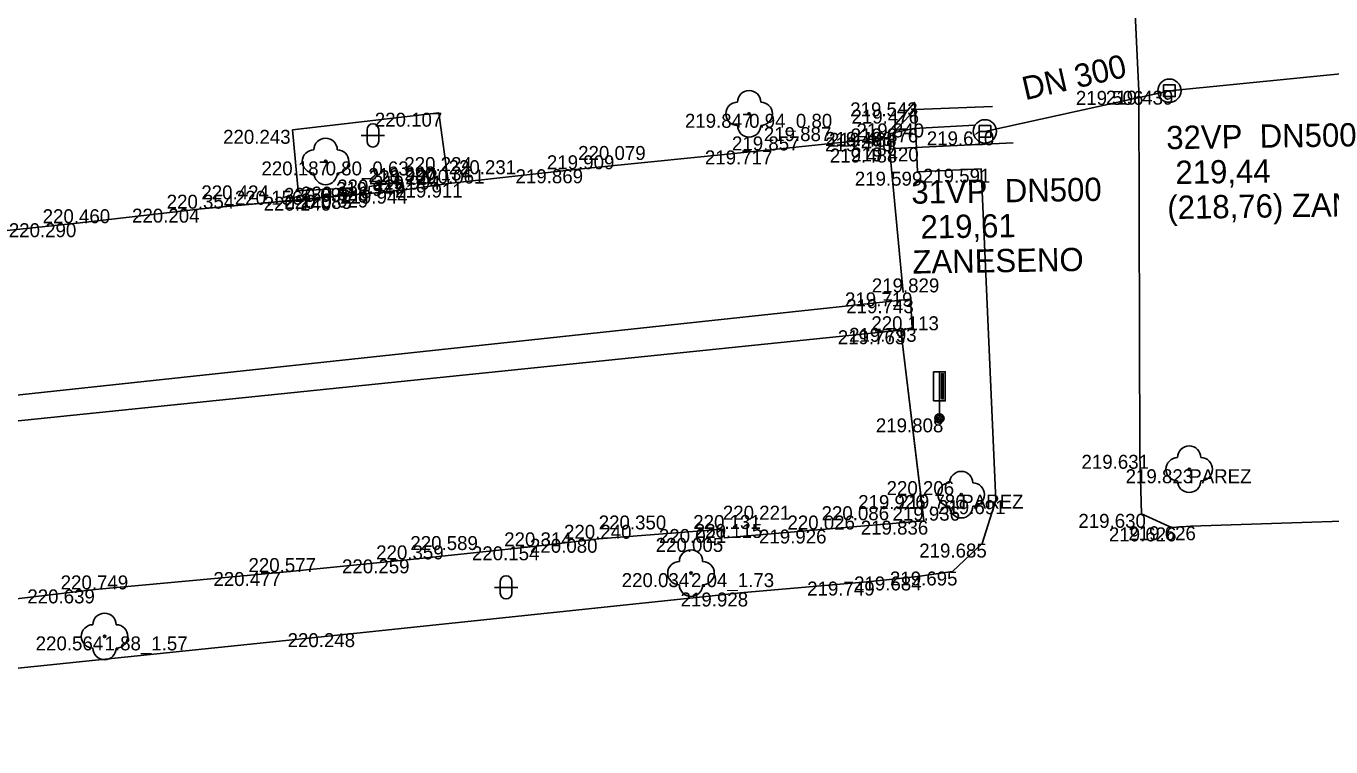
# Model space of a CAD drawing. Extents: x -599516 to -599132, y -1163668 to -1163119.
# Drawn here: x -599267.3 to -599239.27, y -1163495.5 to -1163480.02 of the extents above; entities that cross this region are included whole.
import ezdxf

# ---------------------------------------------------------------- set-up
doc = ezdxf.new("R2010")
doc.units = 0
for name, color, linetype in [('Bod-oznac1', 7, 'Continuous'), ('Bod-oznac2', 7, 'Continuous'), ('Bod-oznac3', 7, 'Continuous'), ('Bod-oznac4', 7, 'Continuous'), ('Bod-vyska1', 7, 'Continuous'), ('Bod-vyska2', 7, 'Continuous'), ('Bod-vyska3', 7, 'Continuous'), ('Bod-vyska4', 7, 'Continuous'), ('Z_cela-hrobu-dolni-linie', 7, 'Continuous'), ('Z_cela-hrobu-horni-linie', 7, 'Continuous'), ('Z_kanalizace-destova', 7, 'Continuous'), ('Z_kanalizace-znacky-vpust', 7, 'Continuous'), ('Z_komunikace', 7, 'Continuous'), ('Z_kultury-znacky', 7, 'Continuous'), ('Z_obvod-kmene-spodek-ve-vysce1_2m', 7, 'Continuous'), ('Z_parez-stromu', 7, 'Continuous'), ('Z_podzemni-obrys-sachty', 7, 'Continuous'), ('Z_stromy-kere', 7, 'Continuous'), ('Z_zdi-ohradni', 7, 'Continuous'), ('Z_zlaby-odvodneni', 7, 'Continuous'), ('Z_zlaby-odvodneni-osa', 7, 'Continuous'), ('Z_zlaby-odvodneni-zakryte-hrany', 7, 'Continuous'), ('Z_znacky-ostatni-orientacni-sloupek', 7, 'Continuous'), ('Z_zpevnene-plochy', 7, 'Continuous')]:
    doc.layers.add(name, color=color, linetype=linetype)

msp = doc.modelspace()

# ---------------------------------------------------------------- linework, layer by layer
at = {"layer": 'Bod-oznac1'}
for p, q in [((-599243.4, -1163481.411), (-599243.4, -1163481.411)), ((-599242.743, -1163481.405), (-599242.743, -1163481.405)), ((-599258.436, -1163481.878), (-599258.436, -1163481.878)), ((-599248.222, -1163481.656), (-599248.222, -1163481.656)), ((-599248.204, -1163481.812), (-599248.204, -1163481.812)), ((-599251.771, -1163481.902), (-599251.771, -1163481.902)), ((-599261.579, -1163482.246), (-599261.579, -1163482.246)), ((-599248.777, -1163482.408), (-599248.777, -1163482.408)), ((-599248.772, -1163482.292), (-599248.772, -1163482.292)), ((-599248.678, -1163482.31), (-599248.678, -1163482.31)), ((-599248.233, -1163482.216), (-599248.233, -1163482.216)), ((-599246.706, -1163482.279), (-599246.706, -1163482.279)), ((-599251.455, -1163482.688), (-599251.455, -1163482.688)), ((-599248.66, -1163482.648), (-599248.66, -1163482.648)), ((-599248.203, -1163482.624), (-599248.203, -1163482.624)), ((-599260.868, -1163482.924), (-599260.868, -1163482.924)), ((-599255.444, -1163483.093), (-599255.444, -1163483.093)), ((-599248.157, -1163483.145), (-599248.157, -1163483.145)), ((-599246.788, -1163483.082), (-599246.788, -1163483.082)), ((-599261.454, -1163483.554), (-599261.454, -1163483.554)), ((-599260.297, -1163483.494), (-599260.297, -1163483.494)), ((-599259.932, -1163483.466), (-599259.932, -1163483.466)), ((-599259.277, -1163483.367), (-599259.277, -1163483.367)), ((-599259.177, -1163483.531), (-599259.177, -1163483.531)), ((-599258.226, -1163483.399), (-599258.226, -1163483.399)), ((-599260.814, -1163483.682), (-599260.814, -1163483.682)), ((-599260.275, -1163483.643), (-599260.275, -1163483.643)), ((-599259.937, -1163483.614), (-599259.937, -1163483.614)), ((-599263.537, -1163483.939), (-599263.537, -1163483.939)), ((-599266.207, -1163484.251), (-599266.207, -1163484.251)), ((-599248.459, -1163485.737), (-599248.459, -1163485.737)), ((-599248.306, -1163485.884), (-599248.306, -1163485.884)), ((-599248.51, -1163486.55), (-599248.51, -1163486.55)), ((-599248.267, -1163486.498), (-599248.267, -1163486.498)), ((-599247.685, -1163488.442), (-599247.685, -1163488.442)), ((-599243.381, -1163489.225), (-599243.381, -1163489.225)), ((-599242.318, -1163489.535), (-599242.318, -1163489.535)), ((-599248.085, -1163490.09), (-599248.085, -1163490.09)), ((-599247.215, -1163490.08), (-599247.215, -1163490.08)), ((-599246.474, -1163490.199), (-599246.474, -1163490.199)), ((-599243.346, -1163490.493), (-599243.346, -1163490.493)), ((-599252.335, -1163490.818), (-599252.335, -1163490.818)), ((-599250.215, -1163490.829), (-599250.215, -1163490.829)), ((-599248.019, -1163490.639), (-599248.019, -1163490.639)), ((-599242.699, -1163490.784), (-599242.699, -1163490.784)), ((-599242.282, -1163490.76), (-599242.282, -1163490.76)), ((-599255.002, -1163491.028), (-599255.002, -1163491.028)), ((-599252.302, -1163491.01), (-599252.302, -1163491.01)), ((-599246.762, -1163491.131), (-599246.762, -1163491.131)), ((-599256.338, -1163491.19), (-599256.338, -1163491.19)), ((-599259.048, -1163491.47), (-599259.048, -1163491.47)), ((-599261.783, -1163491.742), (-599261.783, -1163491.742)), ((-599253.019, -1163491.766), (-599253.019, -1163491.766)), ((-599249.157, -1163491.947), (-599249.157, -1163491.947)), ((-599248.151, -1163491.837), (-599248.151, -1163491.837)), ((-599247.403, -1163491.731), (-599247.403, -1163491.731)), ((-599265.818, -1163492.115), (-599265.818, -1163492.115)), ((-599251.888, -1163492.182), (-599251.888, -1163492.182)), ((-599260.194, -1163493.055), (-599260.194, -1163493.055)), ((-599265.616, -1163493.124), (-599265.616, -1163493.124))]:
    msp.add_line(p, q, dxfattribs=at)
at = {"layer": 'Bod-oznac2'}
for p, q in [((-599248.777, -1163482.408), (-599248.777, -1163482.408)), ((-599251.455, -1163482.688), (-599251.455, -1163482.688)), ((-599255.444, -1163483.093), (-599255.444, -1163483.093)), ((-599259.277, -1163483.367), (-599259.277, -1163483.367)), ((-599259.177, -1163483.531), (-599259.177, -1163483.531)), ((-599258.226, -1163483.399), (-599258.226, -1163483.399)), ((-599259.937, -1163483.614), (-599259.937, -1163483.614)), ((-599263.537, -1163483.939), (-599263.537, -1163483.939)), ((-599266.207, -1163484.251), (-599266.207, -1163484.251)), ((-599248.459, -1163485.737), (-599248.459, -1163485.737)), ((-599248.51, -1163486.55), (-599248.51, -1163486.55)), ((-599248.085, -1163490.09), (-599248.085, -1163490.09)), ((-599252.335, -1163490.818), (-599252.335, -1163490.818)), ((-599250.215, -1163490.829), (-599250.215, -1163490.829)), ((-599248.019, -1163490.639), (-599248.019, -1163490.639)), ((-599255.002, -1163491.028), (-599255.002, -1163491.028)), ((-599252.302, -1163491.01), (-599252.302, -1163491.01)), ((-599256.338, -1163491.19), (-599256.338, -1163491.19)), ((-599259.048, -1163491.47), (-599259.048, -1163491.47)), ((-599261.783, -1163491.742), (-599261.783, -1163491.742)), ((-599265.818, -1163492.115), (-599265.818, -1163492.115))]:
    msp.add_line(p, q, dxfattribs=at)
at = {"layer": 'Bod-oznac3'}
for p, q in [((-599251.455, -1163482.688), (-599251.455, -1163482.688)), ((-599255.444, -1163483.093), (-599255.444, -1163483.093)), ((-599259.177, -1163483.531), (-599259.177, -1163483.531)), ((-599258.226, -1163483.399), (-599258.226, -1163483.399)), ((-599259.937, -1163483.614), (-599259.937, -1163483.614)), ((-599263.537, -1163483.939), (-599263.537, -1163483.939)), ((-599252.335, -1163490.818), (-599252.335, -1163490.818)), ((-599250.215, -1163490.829), (-599250.215, -1163490.829)), ((-599255.002, -1163491.028), (-599255.002, -1163491.028)), ((-599259.048, -1163491.47), (-599259.048, -1163491.47))]:
    msp.add_line(p, q, dxfattribs=at)
at = {"layer": 'Bod-oznac4'}
msp.add_line((-599259.177, -1163483.531), (-599259.177, -1163483.531), dxfattribs=at)
at = {"layer": 'Z_cela-hrobu-dolni-linie'}
for p, q in [((-599248.777, -1163482.408), (-599248.459, -1163485.737)), ((-599248.51, -1163486.55), (-599248.019, -1163490.639))]:
    msp.add_line(p, q, dxfattribs=at)
for points in [[(-599260.275, -1163483.643), (-599259.937, -1163483.614), (-599259.177, -1163483.531), (-599258.226, -1163483.399)], [(-599278.819, -1163493.425), (-599277.091, -1163493.389), (-599275.214, -1163493.173), (-599272.51, -1163492.915), (-599269.858, -1163492.594), (-599268.544, -1163492.436), (-599265.818, -1163492.115), (-599261.783, -1163491.742), (-599259.048, -1163491.47), (-599256.338, -1163491.19), (-599255.002, -1163491.028), (-599252.335, -1163490.818), (-599252.302, -1163491.01), (-599250.215, -1163490.829), (-599248.019, -1163490.639)]]:
    msp.add_lwpolyline(points, dxfattribs=at)
at = {"layer": 'Z_cela-hrobu-horni-linie'}
msp.add_line((-599265.818, -1163492.115), (-599268.544, -1163492.436), dxfattribs=at)
for points in [[(-599270.312, -1163484.682), (-599266.207, -1163484.251), (-599263.537, -1163483.939), (-599263.537, -1163483.939), (-599259.937, -1163483.614), (-599259.937, -1163483.614), (-599259.177, -1163483.531), (-599259.177, -1163483.531), (-599258.226, -1163483.399), (-599258.226, -1163483.399), (-599255.444, -1163483.093), (-599255.444, -1163483.093), (-599251.455, -1163482.688), (-599251.455, -1163482.688), (-599248.777, -1163482.408), (-599248.459, -1163485.737)], [(-599248.51, -1163486.55), (-599248.085, -1163490.09), (-599248.085, -1163490.09), (-599248.019, -1163490.639)], [(-599248.019, -1163490.639), (-599250.215, -1163490.829), (-599250.215, -1163490.829), (-599252.302, -1163491.01), (-599252.335, -1163490.818), (-599252.335, -1163490.818), (-599255.002, -1163491.028), (-599255.002, -1163491.028), (-599256.338, -1163491.19), (-599259.048, -1163491.47), (-599259.048, -1163491.47), (-599261.783, -1163491.742), (-599265.818, -1163492.115)]]:
    msp.add_lwpolyline(points, dxfattribs=at)
at = {"layer": 'Z_kanalizace-destova'}
for p, q in [((-599242.743, -1163481.405), (-599234.094, -1163480.546)), ((-599246.706, -1163482.279), (-599242.743, -1163481.405)), ((-599242.73, -1163481.41), (-599242.73, -1163481.41))]:
    msp.add_line(p, q, dxfattribs=at)
at = {"layer": 'Z_kanalizace-znacky-vpust'}
for p, q in [((-599242.868, -1163481.405), (-599242.618, -1163481.405)), ((-599246.831, -1163482.279), (-599246.581, -1163482.279))]:
    msp.add_line(p, q, dxfattribs=at)
for points in [[(-599242.868, -1163481.28), (-599242.618, -1163481.28), (-599242.618, -1163481.53), (-599242.868, -1163481.53)], [(-599246.831, -1163482.154), (-599246.581, -1163482.154), (-599246.581, -1163482.404), (-599246.831, -1163482.404)]]:
    msp.add_lwpolyline(points, close=True, dxfattribs=at)
at = {"layer": 'Z_komunikace'}
for points in [[(-599243.538, -1163474.658), (-599243.723, -1163474.972), (-599243.67, -1163475.664), (-599243.639, -1163476.428), (-599243.4, -1163481.411), (-599243.381, -1163489.225), (-599243.346, -1163490.493), (-599242.699, -1163490.784), (-599242.282, -1163490.76), (-599236.651, -1163490.572), (-599235.413, -1163490.641), (-599233.862, -1163491.132), (-599232.873, -1163491.765), (-599231.684, -1163492.382), (-599230.881, -1163493.069), (-599229.898, -1163494.138), (-599229.174, -1163495.502), (-599228.7, -1163499.092), (-599228.046, -1163504.018), (-599227.508, -1163512.042), (-599227.073, -1163521.662), (-599227.019, -1163529.722), (-599226.156, -1163541.688)], [(-599248.151, -1163491.837), (-599247.403, -1163491.731), (-599246.762, -1163491.131), (-599246.474, -1163490.199), (-599246.788, -1163483.082), (-599248.157, -1163483.145), (-599248.222, -1163481.656), (-599248.772, -1163482.292), (-599248.777, -1163482.408), (-599251.455, -1163482.688), (-599255.444, -1163483.093), (-599258.226, -1163483.399), (-599258.436, -1163481.878), (-599261.579, -1163482.246), (-599261.454, -1163483.554), (-599260.297, -1163483.494), (-599260.275, -1163483.643), (-599260.814, -1163483.682), (-599263.537, -1163483.939), (-599266.207, -1163484.251), (-599270.117, -1163484.659)], [(-599284.677, -1163495.042), (-599284.334, -1163495.359), (-599283.986, -1163495.474), (-599283.409, -1163495.485), (-599280.161, -1163495.23), (-599278.721, -1163495.276), (-599278.049, -1163495.497), (-599277.594, -1163495.189), (-599276.531, -1163494.884), (-599268.176, -1163493.876), (-599260.194, -1163493.055), (-599251.888, -1163492.182), (-599249.157, -1163491.947), (-599248.151, -1163491.837)]]:
    msp.add_lwpolyline(points, dxfattribs=at)
at = {"layer": 'Z_kultury-znacky'}
for p, q in [((-599260.102, -1163482.366), (-599259.602, -1163482.366)), ((-599259.977, -1163482.241), (-599259.977, -1163482.491)), ((-599259.727, -1163482.241), (-599259.727, -1163482.491)), ((-599257.116, -1163491.946), (-599257.116, -1163492.196)), ((-599256.866, -1163491.946), (-599256.866, -1163492.196)), ((-599257.241, -1163492.071), (-599256.741, -1163492.071))]:
    msp.add_line(p, q, dxfattribs=at)
for centre, start, end in [((-599259.853, -1163482.241), 0, 180), ((-599259.853, -1163482.491), 180, 0), ((-599256.991, -1163491.946), 0, 180), ((-599256.991, -1163492.196), 180, 0)]:
    msp.add_arc(centre, 0.125, start, end, dxfattribs=at)
at = {"layer": 'Z_parez-stromu'}
for centre in [(-599242.318, -1163489.535), (-599247.215, -1163490.08)]:
    msp.add_circle(centre, 0.025, dxfattribs=at)
for centre, start, end in [((-599242.318, -1163489.285), 0, 180), ((-599242.568, -1163489.535), 90, 270), ((-599242.068, -1163489.535), 270, 90), ((-599247.215, -1163489.83), 0, 180), ((-599247.465, -1163490.08), 90, 270), ((-599246.965, -1163490.08), 270, 90), ((-599242.318, -1163489.785), 180, 0), ((-599247.215, -1163490.33), 180, 0)]:
    msp.add_arc(centre, 0.25, start, end, dxfattribs=at)
at = {"layer": 'Z_podzemni-obrys-sachty'}
for centre in [(-599242.743, -1163481.405), (-599246.706, -1163482.279)]:
    msp.add_circle(centre, 0.25, dxfattribs=at)
at = {"layer": 'Z_stromy-kere'}
for centre in [(-599251.771, -1163481.902), (-599260.868, -1163482.924), (-599253.019, -1163491.766), (-599265.616, -1163493.124)]:
    msp.add_circle(centre, 0.025, dxfattribs=at)
for centre, start, end in [((-599251.771, -1163481.652), 0, 180), ((-599252.021, -1163481.902), 90, 270), ((-599251.521, -1163481.902), 270, 90), ((-599251.771, -1163482.152), 180, 0), ((-599260.868, -1163482.674), 0, 180), ((-599261.118, -1163482.924), 90, 270), ((-599260.618, -1163482.924), 270, 90), ((-599260.868, -1163483.174), 180, 0), ((-599253.019, -1163491.516), 0, 180), ((-599253.269, -1163491.766), 90, 270), ((-599252.769, -1163491.766), 270, 90), ((-599253.019, -1163492.016), 180, 0), ((-599265.616, -1163492.874), 0, 180), ((-599265.866, -1163493.124), 90, 270), ((-599265.366, -1163493.124), 270, 90), ((-599265.616, -1163493.374), 180, 0)]:
    msp.add_arc(centre, 0.25, start, end, dxfattribs=at)
at = {"layer": 'Z_zdi-ohradni'}
msp.add_lwpolyline([(-599248.51, -1163486.55), (-599248.267, -1163486.498), (-599248.306, -1163485.884), (-599283.646, -1163489.675), (-599283.573, -1163490.147), (-599248.51, -1163486.55)], dxfattribs=at)
at = {"layer": 'Z_zlaby-odvodneni'}
for points in [[(-599248.204, -1163481.812), (-599248.678, -1163482.31)], [(-599248.678, -1163482.31), (-599248.66, -1163482.648), (-599248.203, -1163482.624)]]:
    msp.add_lwpolyline(points, dxfattribs=at)
at = {"layer": 'Z_zlaby-odvodneni-osa'}
msp.add_lwpolyline([(-599248.233, -1163482.216), (-599248.678, -1163482.31)], dxfattribs=at)
at = {"layer": 'Z_zlaby-odvodneni-zakryte-hrany'}
for p, q in [((-599248.204, -1163481.812), (-599246.543, -1163481.743)), ((-599248.233, -1163482.216), (-599246.921, -1163482.145)), ((-599248.203, -1163482.624), (-599246.103, -1163482.524))]:
    msp.add_line(p, q, dxfattribs=at)
at = {"layer": 'Z_znacky-ostatni-orientacni-sloupek'}
for p, q in [((-599247.81, -1163487.442), (-599247.81, -1163488.067)), ((-599247.81, -1163487.442), (-599247.685, -1163487.442)), ((-599247.81, -1163488.067), (-599247.685, -1163488.067)), ((-599247.685, -1163488.067), (-599247.685, -1163488.342))]:
    msp.add_line(p, q, dxfattribs=at)
for points in [[(-599247.685, -1163488.067), (-599247.56, -1163488.067), (-599247.56, -1163487.442), (-599247.685, -1163487.442)], [(-599247.642, -1163488.025), (-599247.603, -1163488.025), (-599247.603, -1163487.485), (-599247.642, -1163487.485)]]:
    msp.add_lwpolyline(points, close=True, dxfattribs=at)
for radius in [0.1, 0.065, 0.03]:
    msp.add_circle((-599247.685, -1163488.442), radius, dxfattribs=at)
at = {"layer": 'Z_zpevnene-plochy'}
for points in [[(-599259.177, -1163483.531), (-599259.277, -1163483.367), (-599259.932, -1163483.466), (-599259.937, -1163483.614)], [(-599259.177, -1163483.531), (-599259.277, -1163483.367), (-599259.932, -1163483.466)]]:
    msp.add_lwpolyline(points, dxfattribs=at)

# ---------------------------------------------------------------- texts
at = {"layer": 'Bod-vyska1'}
for s, p in [('219.506', (-599244.753, -1163481.711)), ('219.439', (-599244.109, -1163481.705)), ('220.107', (-599259.812, -1163482.178)), ('219.847', (-599253.15, -1163482.202)), ('219.543', (-599249.6, -1163481.956)), ('219.476', (-599249.572, -1163482.112)), ('220.243', (-599263.07, -1163482.546)), ('219.490', (-599250.141, -1163482.708)), ('219.493', (-599250.138, -1163482.592)), ('219.488', (-599250.056, -1163482.61)), ('219.376', (-599249.59, -1163482.516)), ('219.610', (-599247.955, -1163482.579)), ('219.717', (-599252.721, -1163482.988)), ('219.488', (-599250.038, -1163482.948)), ('219.420', (-599249.579, -1163482.924)), ('220.187', (-599262.246, -1163483.224)), ('219.869', (-599256.788, -1163483.393)), ('219.599', (-599249.501, -1163483.445)), ('219.591', (-599248.039, -1163483.382)), ('220.156', (-599262.818, -1163483.854)), ('220.095', (-599261.763, -1163483.794)), ('220.026', (-599261.398, -1163483.766)), ('219.947', (-599260.645, -1163483.667)), ('219.944', (-599260.555, -1163483.831)), ('219.911', (-599259.373, -1163483.699)), ('220.140', (-599262.199, -1163483.982)), ('220.085', (-599261.753, -1163483.943)), ('220.029', (-599261.403, -1163483.914)), ('220.204', (-599265.026, -1163484.239)), ('220.290', (-599267.673, -1163484.551)), ('219.719', (-599249.712, -1163486.037)), ('219.743', (-599249.685, -1163486.184)), ('219.763', (-599249.867, -1163486.85)), ('219.793', (-599249.624, -1163486.798)), ('219.808', (-599249.049, -1163488.742)), ('219.631', (-599244.632, -1163489.525)), ('219.823', (-599243.684, -1163489.835)), ('219.926', (-599249.429, -1163490.39)), ('219.786', (-599248.572, -1163490.38)), ('219.691', (-599247.714, -1163490.499)), ('219.630', (-599244.699, -1163490.793)), ('220.021', (-599253.709, -1163491.118)), ('219.926', (-599251.559, -1163491.129)), ('219.836', (-599249.374, -1163490.939)), ('219.626', (-599244.043, -1163491.084)), ('219.626', (-599243.626, -1163491.06)), ('220.080', (-599256.478, -1163491.328)), ('220.005', (-599253.778, -1163491.31)), ('219.685', (-599248.117, -1163491.431)), ('220.154', (-599257.725, -1163491.49)), ('220.259', (-599260.516, -1163491.77)), ('220.477', (-599263.278, -1163492.042)), ('220.034', (-599254.508, -1163492.066)), ('219.749', (-599250.525, -1163492.247)), ('219.684', (-599249.517, -1163492.137)), ('219.695', (-599248.746, -1163492.031)), ('220.639', (-599267.275, -1163492.415)), ('219.928', (-599253.243, -1163492.482)), ('220.248', (-599261.685, -1163493.355)), ('220.564', (-599267.096, -1163493.424))]:
    msp.add_text(s, height=0.3, dxfattribs=at).set_placement(p)
at = {"layer": 'Bod-vyska2'}
for s, p in [('219.840', (-599249.465, -1163482.408)), ('219.857', (-599252.139, -1163482.688)), ('219.909', (-599256.115, -1163483.093)), ('219.997', (-599259.95, -1163483.367)), ('219.994', (-599259.854, -1163483.531)), ('220.061', (-599258.907, -1163483.399)), ('220.129', (-599260.619, -1163483.614)), ('220.354', (-599264.282, -1163483.939)), ('220.460', (-599266.946, -1163484.251)), ('219.829', (-599249.136, -1163485.737)), ('220.113', (-599249.146, -1163486.55)), ('220.206', (-599248.818, -1163490.09)), ('220.131', (-599252.971, -1163490.818)), ('220.026', (-599250.948, -1163490.829)), ('219.936', (-599248.691, -1163490.639)), ('220.240', (-599255.747, -1163491.028)), ('220.115', (-599252.938, -1163491.01)), ('220.314', (-599257.032, -1163491.19)), ('220.359', (-599259.782, -1163491.47)), ('220.577', (-599262.525, -1163491.742)), ('220.749', (-599266.559, -1163492.115))]:
    msp.add_text(s, height=0.3, dxfattribs=at).set_placement(p)
at = {"layer": 'Bod-vyska3'}
for s, p in [('219.887', (-599251.455, -1163482.488)), ('220.079', (-599255.444, -1163482.893)), ('220.231', (-599258.226, -1163483.199)), ('220.209', (-599259.937, -1163483.414)), ('220.134', (-599259.177, -1163483.331)), ('220.424', (-599263.537, -1163483.739)), ('220.350', (-599255.002, -1163490.828)), ('220.221', (-599252.335, -1163490.618)), ('220.086', (-599250.215, -1163490.629)), ('220.589', (-599259.048, -1163491.27))]:
    msp.add_text(s, height=0.3, dxfattribs=at).set_placement(p)
at = {"layer": 'Bod-vyska4'}
msp.add_text('220.224', height=0.3, dxfattribs=at).set_placement((-599259.177, -1163483.131))
at = {"layer": 'Z_kanalizace-destova'}
for s, rotation, p in [('DN 300', 13.0034, (-599245.84, -1163481.612)), ('32VP  DN500   ', 0.8872, (-599242.808, -1163482.663)), (' 219,44', 0.8872, (-599242.796, -1163483.413)), ('31VP  DN500   ', 0.8872, (-599248.283, -1163483.834)), ('(218,76) ZANESENO', 0.8872, (-599242.785, -1163484.163)), (' 219,61', 0.8872, (-599248.271, -1163484.584)), ('ZANESENO', 0.8872, (-599248.26, -1163485.334))]:
    msp.add_text(s, height=0.5, rotation=rotation, dxfattribs=at).set_placement(p)
at = {"layer": 'Z_obvod-kmene-spodek-ve-vysce1_2m'}
for s, p in [('0.94_0.80', (-599251.771, -1163482.202)), ('0.80_0.63', (-599260.868, -1163483.224)), ('PAREZ', (-599242.318, -1163489.835)), ('PAREZ', (-599247.215, -1163490.38)), ('2.04_1.73', (-599253.019, -1163492.066)), ('1.88_1.57', (-599265.616, -1163493.424))]:
    msp.add_text(s, height=0.3, dxfattribs=at).set_placement(p)

doc.saveas('drawing.dxf')
